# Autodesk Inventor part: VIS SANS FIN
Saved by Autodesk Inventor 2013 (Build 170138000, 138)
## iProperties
Created: 2012-12
Part Number: VIS SANS FIN
Material: Générique
Document SubType Name: Modeling
Designer: jost thierry
Density: 1 g/cm^3
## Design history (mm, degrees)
node "VIS SANS FIN1"
node "VIS SANS FIN"
node "Base1"
